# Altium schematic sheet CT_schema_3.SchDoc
size 461 x 327 mm
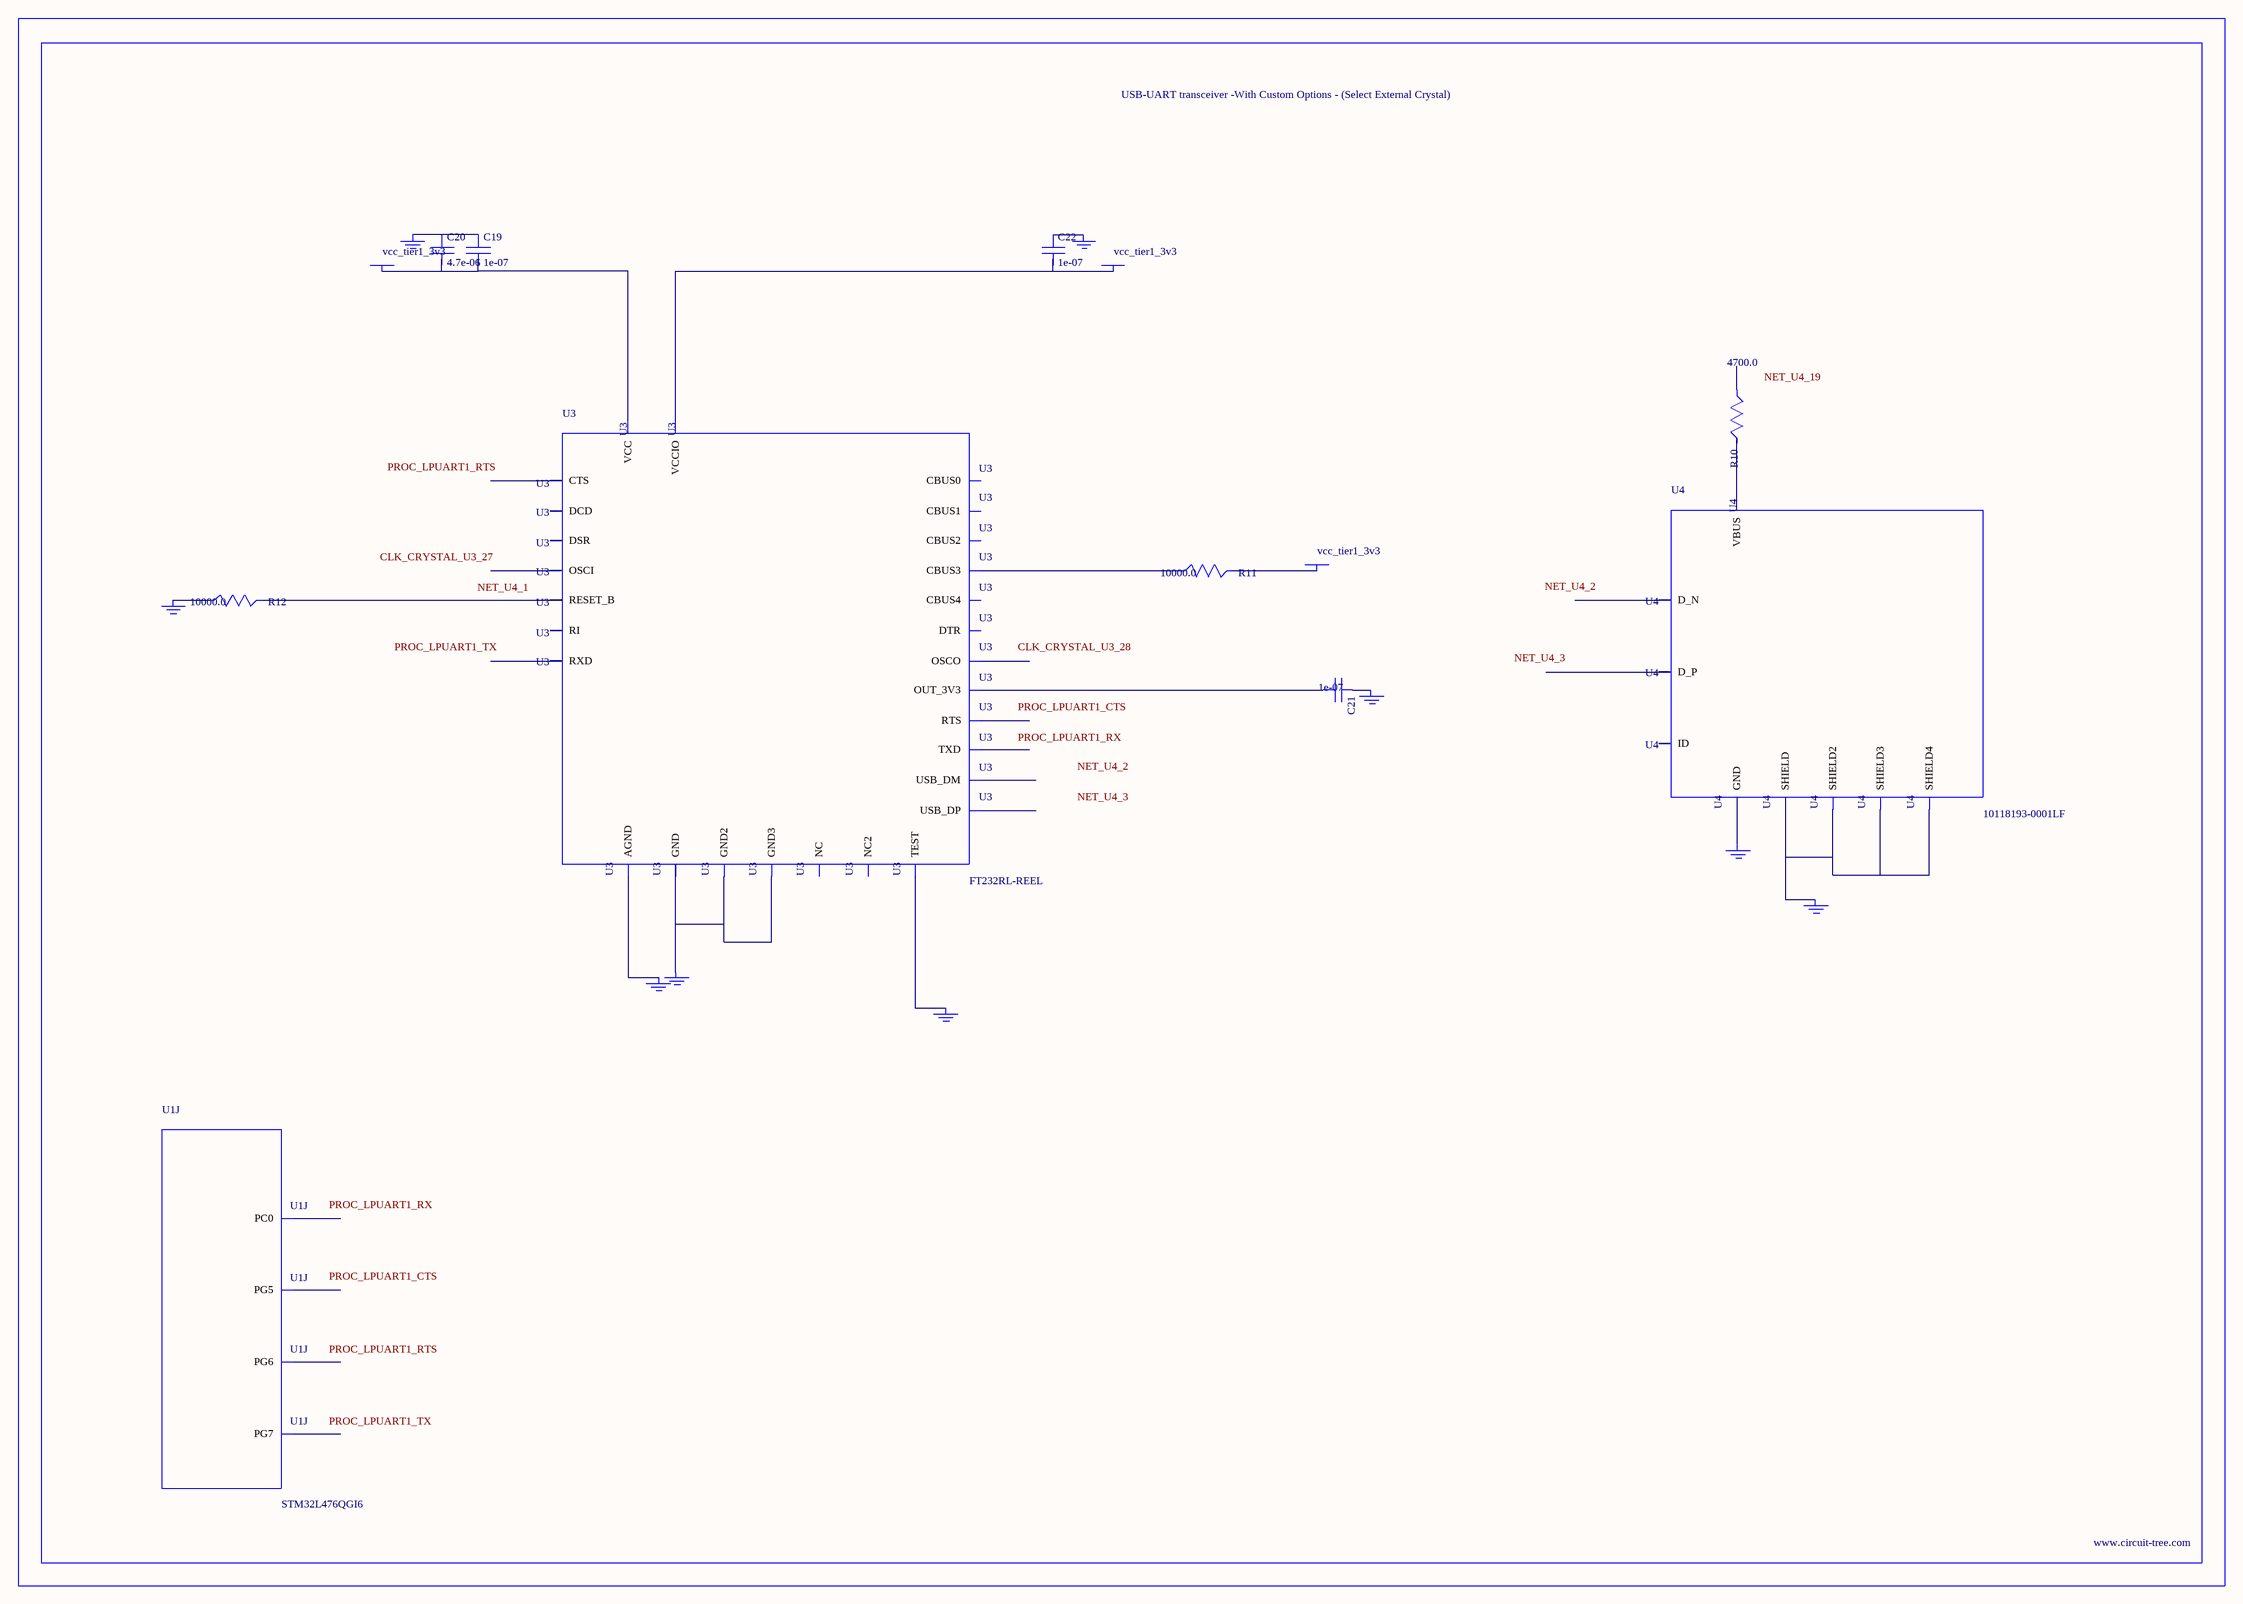
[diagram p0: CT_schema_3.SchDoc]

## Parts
BORDER2  (no value)
C19  1e-07  [C0402]
C20  4.7e-06  [C0805]
C21  1e-07  [C0402]
C22  1e-07  [C0402]
GND_INSTANCE_2_0  (no value)
GND_INSTANCE_2_1  (no value)
GND_INSTANCE_2_2  (no value)
GND_INSTANCE_2_3  (no value)
GND_INSTANCE_2_4  (no value)
GND_INSTANCE_2_5  (no value)
GND_INSTANCE_2_6  (no value)
GND_INSTANCE_2_7  (no value)
GND_INSTANCE_2_8  (no value)
POWER_INSTANCE_2_0  vcc_tier1_3v3
POWER_INSTANCE_2_1  vcc_tier1_3v3
POWER_INSTANCE_2_2  vcc_tier1_3v3
R10  4700.0  [R0603]
R11  10000.0  [R0603]
R12  10000.0  [R0603]
U1  STM32L476QGI6  [UFBGA132]  (part J of 12)
U3  FT232RL-REEL  [SSOP-28]
U4  10118193-0001LF  [FCI_10118193-0001LF]

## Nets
NetC19_1: C19.1 C20.1 GND_INSTANCE_2_3.0(GND)
NetC19_2: C19.2 C20.2 POWER_INSTANCE_2_2.0(PWR) U3.20(VCC)
NetC21_1: C21.1 GND_INSTANCE_2_1.0(GND)
NetC21_2: C21.2 U3.17(OUT_3V3)
NetC22_1: C22.1 GND_INSTANCE_2_0.0(GND)
NetC22_2: C22.2 POWER_INSTANCE_2_0.0(PWR) U3.4(VCCIO)
NetGND_INSTANCE_2_2_0: GND_INSTANCE_2_2.0(GND) R12.1
NetGND_INSTANCE_2_4_0: GND_INSTANCE_2_4.0(GND) U3.25(AGND)
NetGND_INSTANCE_2_5_0: GND_INSTANCE_2_5.0(GND) U3.26(TEST)
NetGND_INSTANCE_2_6_0: GND_INSTANCE_2_6.0(GND) U3.7(GND) U3.18(GND2) U3.21(GND3)
NetGND_INSTANCE_2_7_0: GND_INSTANCE_2_7.0(GND) U4.6(SHIELD) U4.7(SHIELD2) U4.8(SHIELD3) U4.9(SHIELD4)
NetGND_INSTANCE_2_8_0: GND_INSTANCE_2_8.0(GND) U4.5(GND)
NetPOWER_INSTANCE_2_1_0: POWER_INSTANCE_2_1.0(PWR) R11.2
NetR10_2: R10.2 U4.1(VBUS)
NetR11_1: R11.1 U3.14(CBUS3)
NetR12_2: R12.2 U3.19(RESET_B)

Not connected (* = marked no-connect by the designer): R10 1; U1 E9(PG5) G4(PG6) H1(PC0) H4(PG7); U3 1(TXD) 2(DTR) 3(RTS) 5(RXD) 6(RI) 8(NC) 9(DSR) 10(DCD) 11(CTS) 12(CBUS4) 13(CBUS2) 15(USB_DP) 16(USB_DM) 22(CBUS1) 23(CBUS0) 24(NC2) 27(OSCI) 28(OSCO); U4 2(D_N) 3(D_P) 4(ID)

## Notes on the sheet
- Labels drawn without touching a wire or pin: CLK_CRYSTAL_U3_27, CLK_CRYSTAL_U3_28, NET_U4_1, NET_U4_2, NET_U4_3, NET_U4_19, PROC_LPUART1_CTS, PROC_LPUART1_RTS, PROC_LPUART1_RX, PROC_LPUART1_TX

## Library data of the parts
BORDER2 = BORDER_PAGE2
C19 C21 C22 = C0402C104K3RACTU
C20 = C0805C475K4RACTU
GND_INSTANCE_2_0-GND_INSTANCE_2_8 = GND
POWER_INSTANCE_2_0-POWER_INSTANCE_2_2 = PWR
R10 = RC0603JR-074K7L
R11 R12 = RC0603JR-0710KL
